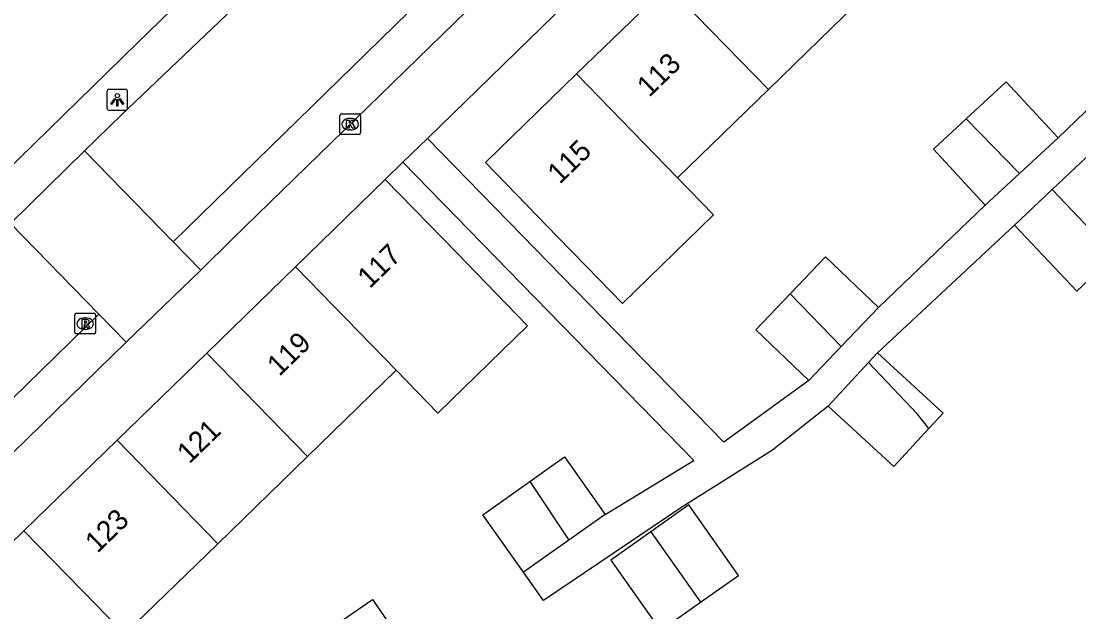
# Model space of a CAD drawing. Extents: x 159222 to 160346, y 381249 to 382166.
# Drawn here: x 159554.2 to 159605.3, y 381433.3 to 381461.9 of the extents above; entities that cross this region are included whole.
import ezdxf

# ---------------------------------------------------------------- set-up
doc = ezdxf.new("R2010")
doc.units = 0
for name, color, linetype in [('IMGEO_Kolk', 7, 'Continuous'), ('IMGEO_Lichtpunt', 7, 'Continuous'), ('IMGEO_Pand', 7, 'Continuous'), ('IMGEO_Pand_nummerreeks', 7, 'Continuous'), ('IMGEO_Rijbaan_lokaal_gesloten', 7, 'Continuous'), ('IMGEO_Rijbaan_lokaal_open', 7, 'Continuous'), ('IMGEO_Rioolput', 7, 'Continuous'), ('IMGEO_Voetpad_open', 7, 'Continuous')]:
    doc.layers.add(name, color=color, linetype=linetype)

msp = doc.modelspace()

# ---------------------------------------------------------------- linework, layer by layer
at = {"layer": 'IMGEO_Kolk'}
for p, q in [((159569.62, 381456.491), (159569.62, 381457.343)), ((159569.695, 381457.417), (159570.547, 381457.417)), ((159570.108, 381457.197), (159570.133, 381457.197)), ((159570.621, 381457.343), (159570.621, 381456.491)), ((159570.131, 381456.637), (159570.106, 381456.637)), ((159570.547, 381456.417), (159569.695, 381456.417))]:
    msp.add_line(p, q, dxfattribs=at)
for points in [[(159569.62, 381456.491), (159569.62, 381457.343)], [(159569.695, 381457.417), (159570.547, 381457.417)], [(159569.941, 381457.117), (159570.064, 381457.117), (159570.064, 381456.966), (159570.194, 381457.117), (159570.358, 381457.117), (159570.212, 381456.966), (159570.365, 381456.717), (159570.213, 381456.717), (159570.128, 381456.881), (159570.064, 381456.814), (159570.064, 381456.717), (159569.941, 381456.717), (159569.941, 381457.117)], [(159570.621, 381457.343), (159570.621, 381456.491)], [(159570.547, 381456.417), (159569.695, 381456.417)]]:
    msp.add_lwpolyline(points, dxfattribs=at)
for centre, start, end in [((159569.697, 381457.341), 91.552, 178.448), ((159569.697, 381457.341), 91.552, 178.448), ((159570.545, 381457.341), 1.552, 88.448), ((159570.545, 381457.341), 1.552, 88.448), ((159569.697, 381456.493), 181.552, 268.448), ((159569.697, 381456.493), 181.552, 268.448), ((159570.545, 381456.493), 271.552, 358.448), ((159570.545, 381456.493), 271.552, 358.448)]:
    msp.add_arc(centre, 0.0765, start, end, dxfattribs=at)
for centre, major_axis, ratio, start_param, end_param in [((159570.107, 381456.917), (-0.387, 0.002), 0.722429, 4.712389, 7.853982), ((159570.132, 381456.917), (-0.39, 0.002), 0.717154, 1.570796, 4.712389)]:
    msp.add_ellipse(centre, major_axis=major_axis, ratio=ratio, start_param=start_param, end_param=end_param, dxfattribs=at)
at = {"layer": 'IMGEO_Lichtpunt'}
for p, q in [((159559.265, 381458.594), (159558.457, 381458.594)), ((159559.265, 381458.594), (159558.457, 381458.594)), ((159558.363, 381458.499), (159558.363, 381457.692)), ((159558.363, 381458.499), (159558.363, 381457.692)), ((159559.359, 381457.692), (159559.359, 381458.499)), ((159559.359, 381457.692), (159559.359, 381458.499)), ((159558.457, 381457.598), (159559.265, 381457.598)), ((159558.457, 381457.598), (159559.265, 381457.598))]:
    msp.add_line(p, q, dxfattribs=at)
for points in [[(159558.737, 381458.163), (159558.776, 381458.135), (159558.588, 381457.873), (159558.55, 381457.9), (159558.737, 381458.163)], [(159558.839, 381458.115), (159558.886, 381458.115), (159558.886, 381457.793), (159558.839, 381457.793), (159558.839, 381458.115)], [(159558.949, 381458.135), (159558.987, 381458.162), (159559.174, 381457.9), (159559.135, 381457.872), (159558.949, 381458.135)]]:
    msp.add_lwpolyline(points, dxfattribs=at)
msp.add_circle((159558.862, 381458.297), 0.0994, dxfattribs=at)
for centre, start, end in [((159558.457, 381458.499), 90, 180), ((159558.457, 381458.499), 90, 180), ((159559.265, 381458.499), 0, 90), ((159559.265, 381458.499), 0, 90), ((159558.457, 381457.692), 180, 270), ((159558.457, 381457.692), 180, 270), ((159559.265, 381457.692), 270, 0), ((159559.265, 381457.692), 270, 360)]:
    msp.add_arc(centre, 0.0946, start, end, dxfattribs=at)
at = {"layer": 'IMGEO_Pand'}
for points in [[(159581.064, 381459.344), (159585.454, 381463.613)], [(159590.335, 381458.594), (159585.454, 381463.613)], [(159594.605, 381462.747), (159590.335, 381458.594)], [(159585.945, 381454.325), (159587.684, 381452.537), (159583.279, 381448.252), (159581.539, 381450.041), (159580.144, 381451.476), (159576.658, 381455.06), (159581.064, 381459.344)], [(159585.945, 381454.325), (159581.064, 381459.344)], [(159590.335, 381458.594), (159585.945, 381454.325)], [(159599.892, 381457.17), (159601.833, 381458.969), (159604.34, 381456.263)], [(159600.816, 381452.997), (159598.308, 381455.703), (159599.892, 381457.17)], [(159599.892, 381457.17), (159602.464, 381454.524)], [(159604.34, 381456.263), (159602.464, 381454.524)], [(159604.057, 381453.762), (159605.693, 381455.306)], [(159602.464, 381454.524), (159600.816, 381452.997)], [(159567.473, 381450.018), (159571.816, 381454.242)], [(159571.816, 381454.242), (159575.301, 381450.657), (159576.682, 381449.237), (159578.697, 381447.165), (159574.353, 381442.94), (159572.338, 381445.013)], [(159602.223, 381452.032), (159604.057, 381453.762)], [(159607.017, 381450.519), (159606.939, 381450.72), (159604.057, 381453.762)], [(159607.017, 381450.519), (159605.236, 381448.839), (159602.223, 381452.032)], [(159591.381, 381448.704), (159593.098, 381450.497), (159595.66, 381448.044)], [(159563.183, 381445.848), (159567.473, 381450.018)], [(159567.473, 381450.018), (159572.338, 381445.013)], [(159592.283, 381444.518), (159589.721, 381446.971), (159591.381, 381448.704)], [(159591.381, 381448.704), (159593.855, 381446.16)], [(159595.66, 381448.044), (159593.855, 381446.16)], [(159558.85, 381441.633), (159563.183, 381445.848)], [(159568.049, 381440.842), (159563.183, 381445.848)], [(159593.855, 381446.16), (159592.283, 381444.518)], [(159595.176, 381445.396), (159595.601, 381445.858)], [(159595.601, 381445.858), (159598.776, 381442.936), (159598.096, 381442.197)], [(159593.23, 381443.282), (159595.176, 381445.396)], [(159598.096, 381442.197), (159597.545, 381442.895), (159595.176, 381445.396)], [(159572.338, 381445.013), (159568.049, 381440.842)], [(159598.096, 381442.197), (159596.405, 381440.36), (159593.23, 381443.282)], [(159554.351, 381437.259), (159558.85, 381441.633)], [(159563.715, 381436.628), (159558.85, 381441.633)], [(159568.049, 381440.842), (159563.715, 381436.628)], [(159578.803, 381439.636), (159580.482, 381440.824), (159582.451, 381438.042)], [(159578.501, 381435.246), (159576.531, 381438.028), (159578.803, 381439.636)], [(159578.803, 381439.636), (159580.694, 381436.798)], [(159587.057, 381433.799), (159588.892, 381435.098), (159586.481, 381438.505), (159584.646, 381437.206)], [(159582.451, 381438.042), (159580.694, 381436.798)], [(159563.715, 381436.628), (159559.218, 381432.254), (159557.837, 381433.675), (159554.351, 381437.259)], [(159584.646, 381437.206), (159582.711, 381435.836), (159585.122, 381432.43), (159587.057, 381433.799)], [(159584.646, 381437.206), (159587.057, 381433.799)], [(159580.694, 381436.798), (159578.501, 381435.246)], [(159569.288, 381432.615), (159571.201, 381433.928), (159573.28, 381430.897)]]:
    msp.add_lwpolyline(points, dxfattribs=at)
at = {"layer": 'IMGEO_Rijbaan_lokaal_gesloten'}
for points in [[(159561.561, 381451.233), (159605.042, 381493.695)], [(159583.978, 381480.527), (159583.4, 381481.11), (159579.617, 381477.325), (159573.71, 381471.509), (159568.824, 381466.734), (159567.162, 381465.109), (159559.073, 381457.375), (159557.278, 381455.629)], [(159534.231, 381424.544), (159557.976, 381447.733)]]:
    msp.add_lwpolyline(points, dxfattribs=at)
at = {"layer": 'IMGEO_Rijbaan_lokaal_open'}
for points in [[(159553.707, 381452.118), (159557.278, 381455.629)], [(159557.278, 381455.629), (159561.561, 381451.233)], [(159557.976, 381447.733), (159553.707, 381452.118)], [(159561.561, 381451.233), (159562.895, 381449.863)], [(159562.895, 381449.863), (159559.294, 381446.379)], [(159559.294, 381446.379), (159557.976, 381447.733)]]:
    msp.add_lwpolyline(points, dxfattribs=at)
at = {"layer": 'IMGEO_Rioolput'}
for p, q in [((159556.811, 381446.845), (159556.811, 381447.697)), ((159556.886, 381447.771), (159557.738, 381447.771)), ((159557.299, 381447.551), (159557.324, 381447.551)), ((159557.812, 381447.697), (159557.812, 381446.845)), ((159557.738, 381446.771), (159556.886, 381446.771)), ((159557.322, 381446.991), (159557.297, 381446.991))]:
    msp.add_line(p, q, dxfattribs=at)
for points in [[(159556.811, 381446.845), (159556.811, 381447.697)], [(159556.886, 381447.771), (159557.738, 381447.771)], [(159557.4, 381447.469), (159557.148, 381447.471), (159557.148, 381447.071)], [(159557.326, 381447.39), (159557.272, 381447.39), (159557.272, 381447.309)], [(159557.272, 381447.309), (159557.324, 381447.309)], [(159557.812, 381447.697), (159557.812, 381446.845)], [(159557.738, 381446.771), (159556.886, 381446.771)], [(159557.148, 381447.071), (159557.272, 381447.071), (159557.272, 381447.233), (159557.283, 381447.233)], [(159557.33, 381447.204), (159557.401, 381447.071), (159557.541, 381447.071), (159557.476, 381447.197)]]:
    msp.add_lwpolyline(points, dxfattribs=at)
for centre, radius, start, end in [((159556.888, 381447.695), 0.0765, 91.552, 178.448), ((159556.888, 381447.695), 0.0765, 91.552, 178.448), ((159557.308, 381447.498), 0.19, 274.7715, 282.9687), ((159557.332, 381447.294), 0.0964, 77.0061, 93.1865), ((159557.346, 381447.351), 0.0378, 276.6634, 79.6772), ((159557.399, 381447.359), 0.109, 350.3612, 89.416), ((159557.397, 381447.359), 0.112, 277.5842, 350.9817), ((159557.736, 381447.695), 0.0765, 1.552, 88.448), ((159557.736, 381447.695), 0.0765, 1.552, 88.448), ((159556.888, 381446.847), 0.0765, 181.552, 268.448), ((159556.888, 381446.847), 0.0765, 181.552, 268.448), ((159557.282, 381447.18), 0.0533, 26.0293, 88.6989), ((159557.381, 381447.144), 0.108, 29.5134, 73.7905), ((159557.736, 381446.847), 0.0765, 271.552, 358.448), ((159557.736, 381446.847), 0.0765, 271.552, 358.448)]:
    msp.add_arc(centre, radius, start, end, dxfattribs=at)
for centre, major_axis, ratio, start_param, end_param in [((159557.298, 381447.271), (-0.387, 0.002), 0.722429, 4.712389, 7.853982), ((159557.323, 381447.271), (-0.39, 0.002), 0.717154, 1.570796, 4.712389)]:
    msp.add_ellipse(centre, major_axis=major_axis, ratio=ratio, start_param=start_param, end_param=end_param, dxfattribs=at)
at = {"layer": 'IMGEO_Voetpad_open'}
for points in [[(159609.226, 381490.692), (159573.857, 381456.231)], [(159582.905, 381469.38), (159564.426, 381451.368), (159562.895, 381449.863)], [(159535.841, 381445.829), (159537.906, 381443.641), (159537.412, 381443.132), (159539.479, 381440.948), (159542.513, 381443.914), (159544.065, 381445.432), (159559.843, 381460.857), (159562.025, 381462.991)], [(159609.529, 381461.259), (159604.34, 381456.263)], [(159573.857, 381456.231), (159572.669, 381455.073)], [(159592.283, 381444.518), (159588.177, 381441.534), (159573.857, 381456.231)], [(159572.669, 381455.073), (159571.816, 381454.242)], [(159582.451, 381438.042), (159586.41, 381440.459), (159586.723, 381440.649), (159572.669, 381455.073)], [(159600.816, 381452.997), (159595.66, 381448.044)], [(159602.223, 381452.032), (159595.601, 381445.858)], [(159559.294, 381446.379), (159552.45, 381439.703), (159537.76, 381425.355), (159537.603, 381425.195), (159537.586, 381425.175), (159537.529, 381425.116), (159537.466, 381425.062), (159537.4, 381425.014), (159537.329, 381424.973), (159537.255, 381424.937), (159537.177, 381424.909), (159537.098, 381424.887), (159537.017, 381424.873), (159536.935, 381424.866), (159534.67, 381424.666), (159534.512, 381424.636), (159534.357, 381424.592), (159534.231, 381424.544)], [(159593.23, 381443.282), (159590.537, 381441.145), (159586.098, 381438.369), (159579.462, 381433.888), (159578.501, 381435.246)], [(159554.351, 381437.259), (159544.261, 381427.431)]]:
    msp.add_lwpolyline(points, dxfattribs=at)

# ---------------------------------------------------------------- texts
at = {"layer": 'IMGEO_Pand_nummerreeks'}
for s, rotation, p in [('113', 44.2008, (159584.575, 381458.185)), ('115', 44.2008, (159580.25, 381453.979)), ('117', 44.198, (159571.064, 381448.935)), ('119', 44.1984, (159566.696, 381444.689)), ('121', 44.1984, (159562.345, 381440.459)), ('123', 44.1984, (159557.898, 381436.134))]:
    msp.add_text(s, height=1, rotation=rotation, dxfattribs=at).set_placement(p)

doc.saveas('drawing.dxf')
